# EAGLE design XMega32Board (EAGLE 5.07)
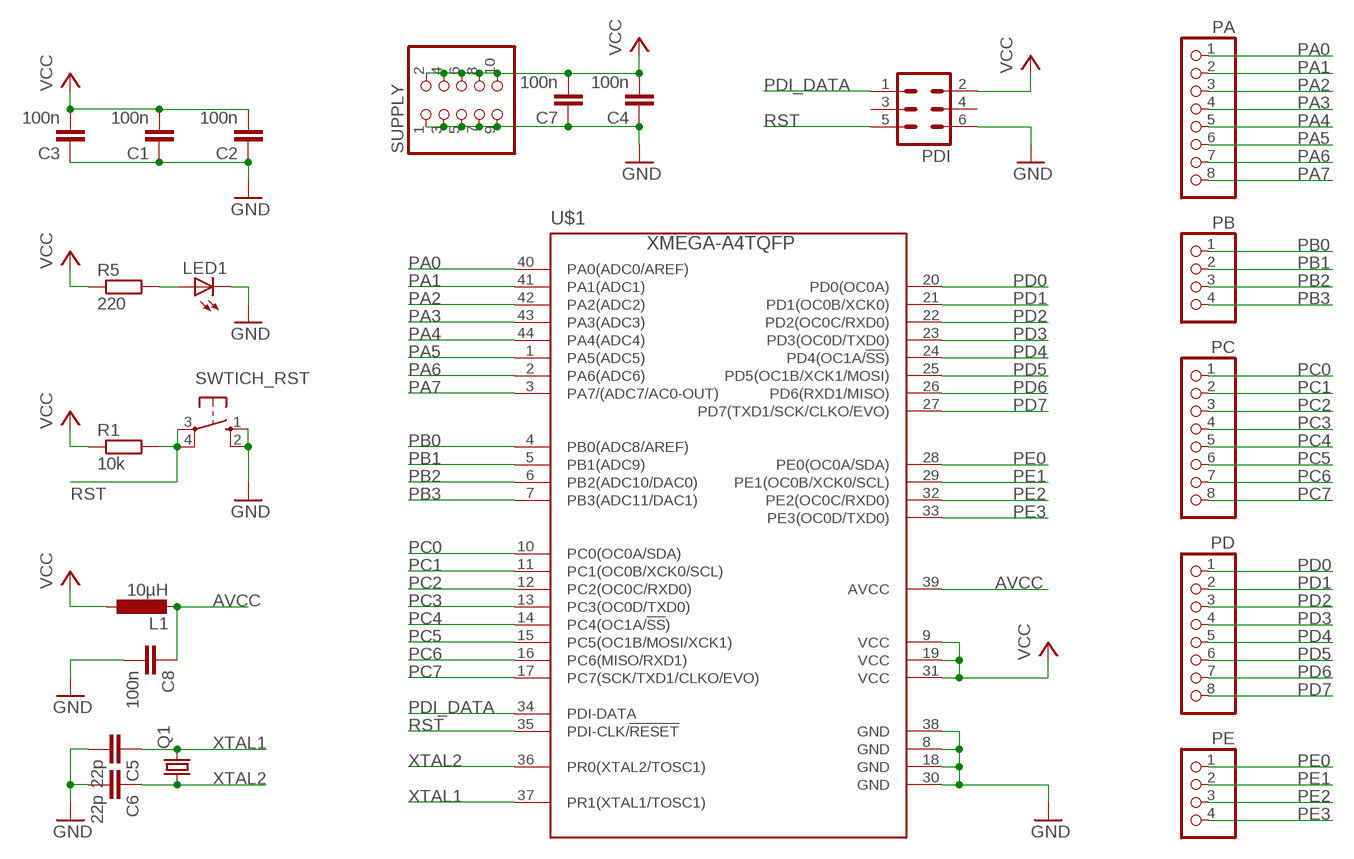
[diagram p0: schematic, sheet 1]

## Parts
C1  100n  C-EUC0805  [C0805]
C2  100n  C-EUC0805  [C0805]
C3  100n  C-EUC0805  [C0805]
C4  100n  C-EUC0805  [C0805]
C5  22p  C-EUC0805  [C0805]
C6  22p  C-EUC0805  [C0805]
C7  100n  C-EUC0805  [C0805]
C8  100n  C-EUC0805  [C0805]
L1  10µH  L-EUL2012C  [L2012C]
LED1  LED3MM  [LED3MM]
PA  PINHD-1X8  [1X08]
PB  PINHD-1X4  [1X04]
PC  PINHD-1X8  [1X08]
PD  PINHD-1X8  [1X08]
PDI  ML6  [ML6]
PE  PINHD-1X4  [1X04]
Q1  CRYSTALHC49S  [HC49/S]
R1  10k  R-EU_R0805  [R0805]
R5  220  R-EU_R0805  [R0805]
SUPPLY  PINHD-2X5  [2X05]
SWTICH_RST  10-XX  [B3F-10XX]
U$1  XMEGA-A4TQFP  [TQFP44]

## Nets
AVCC: C8.1 L1.2 U$1.39(AVCC)
GND: C1.1 C2.1 C3.1 C4.1 C5.2 C6.2 C7.1 C8.2 LED1.K(C) PDI.6 SUPPLY.1 SUPPLY.3 SUPPLY.5 SUPPLY.7 SUPPLY.9 SWTICH_RST.1(S) SWTICH_RST.2(S1) U$1.8(GND) U$1.18(GND) U$1.30(GND) U$1.38(GND)
N$6: LED1.A R5.2
PA0: PA.1 U$1.40(PA0(ADC0/AREF))
PA1: PA.2 U$1.41(PA1(ADC1))
PA2: PA.3 U$1.42(PA2(ADC2))
PA3: PA.4 U$1.43(PA3(ADC3))
PA4: PA.5 U$1.44(PA4(ADC4))
PA5: PA.6 U$1.1(PA5(ADC5))
PA6: PA.7 U$1.2(PA6(ADC6))
PA7: PA.8 U$1.3(PA7/(ADC7/AC0-OUT))
PB0: PB.1 U$1.4(PB0(ADC8/AREF))
PB1: PB.2 U$1.5(PB1(ADC9))
PB2: PB.3 U$1.6(PB2(ADC10/DAC0))
PB3: PB.4 U$1.7(PB3(ADC11/DAC1))
PC0: PC.1 U$1.10(PC0(OC0A/SDA))
PC1: PC.2 U$1.11(PC1(OC0B/XCK0/SCL))
PC2: PC.3 U$1.12(PC2(OC0C/RXD0))
PC3: PC.4 U$1.13(PC3(OC0D/TXD0))
PC4: PC.5 U$1.14(PC4(OC1A/!SS!))
PC5: PC.6 U$1.15(PC5(OC1B/MOSI/XCK1))
PC6: PC.7 U$1.16(PC6(MISO/RXD1))
PC7: PC.8 U$1.17(PC7(SCK/TXD1/CLKO/EVO))
PD0: PD.1 U$1.20(PD0(OC0A))
PD1: PD.2 U$1.21(PD1(OC0B/XCK0))
PD2: PD.3 U$1.22(PD2(OC0C/RXD0))
PD3: PD.4 U$1.23(PD3(OC0D/TXD0))
PD4: PD.5 U$1.24(PD4(OC1A/!SS!))
PD5: PD.6 U$1.25(PD5(OC1B/XCK1/MOSI))
PD6: PD.7 U$1.26(PD6(RXD1/MISO))
PD7: PD.8 U$1.27(PD7(TXD1/SCK/CLKO/EVO))
PDI_DATA: PDI.1 U$1.34(PDI-DATA)
PE0: PE.1 U$1.28(PE0(OC0A/SDA))
PE1: PE.2 U$1.29(PE1(OC0B/XCK0/SCL))
PE2: PE.3 U$1.32(PE2(OC0C/RXD0))
PE3: PE.4 U$1.33(PE3(OC0D/TXD0))
RST: PDI.5 R1.2 SWTICH_RST.3(P) SWTICH_RST.4(P1) U$1.35(PDI-CLK/!RESET)
VCC: C1.2 C2.2 C3.2 C4.2 C7.2 L1.1 PDI.2 R1.1 R5.1 SUPPLY.2 SUPPLY.4 SUPPLY.6 SUPPLY.8 SUPPLY.10 U$1.9(VCC) U$1.19(VCC) U$1.31(VCC)
XTAL1: C5.1 Q1.2 U$1.37(PR1(XTAL1/TOSC1))
XTAL2: C6.1 Q1.1 U$1.36(PR0(XTAL2/TOSC1))
Unconnected: PDI.3 PDI.4

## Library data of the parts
C1-C8 = rcl:C-EU: CAPACITOR, European symbol
L1 = rcl:L-EU: INDUCTOR, European symbol
LED1 = led:LED: LED
PA PC PD = pinhead:PINHD-1X8: PIN HEADER
PB PE = pinhead:PINHD-1X4: PIN HEADER
PDI = con-harting-ml:ML6: HARTING
Q1 = crystal:CRYSTAL: CRYSTAL
R1 R5 = rcl:R-EU_: RESISTOR, European symbol
SUPPLY = pinhead:PINHD-2X5: PIN HEADER
SWTICH_RST = switch-omron:10-XX: OMRON SWITCH
U$1 = avr-7:XMEGA-A4: Atmel XMega A4 series processor

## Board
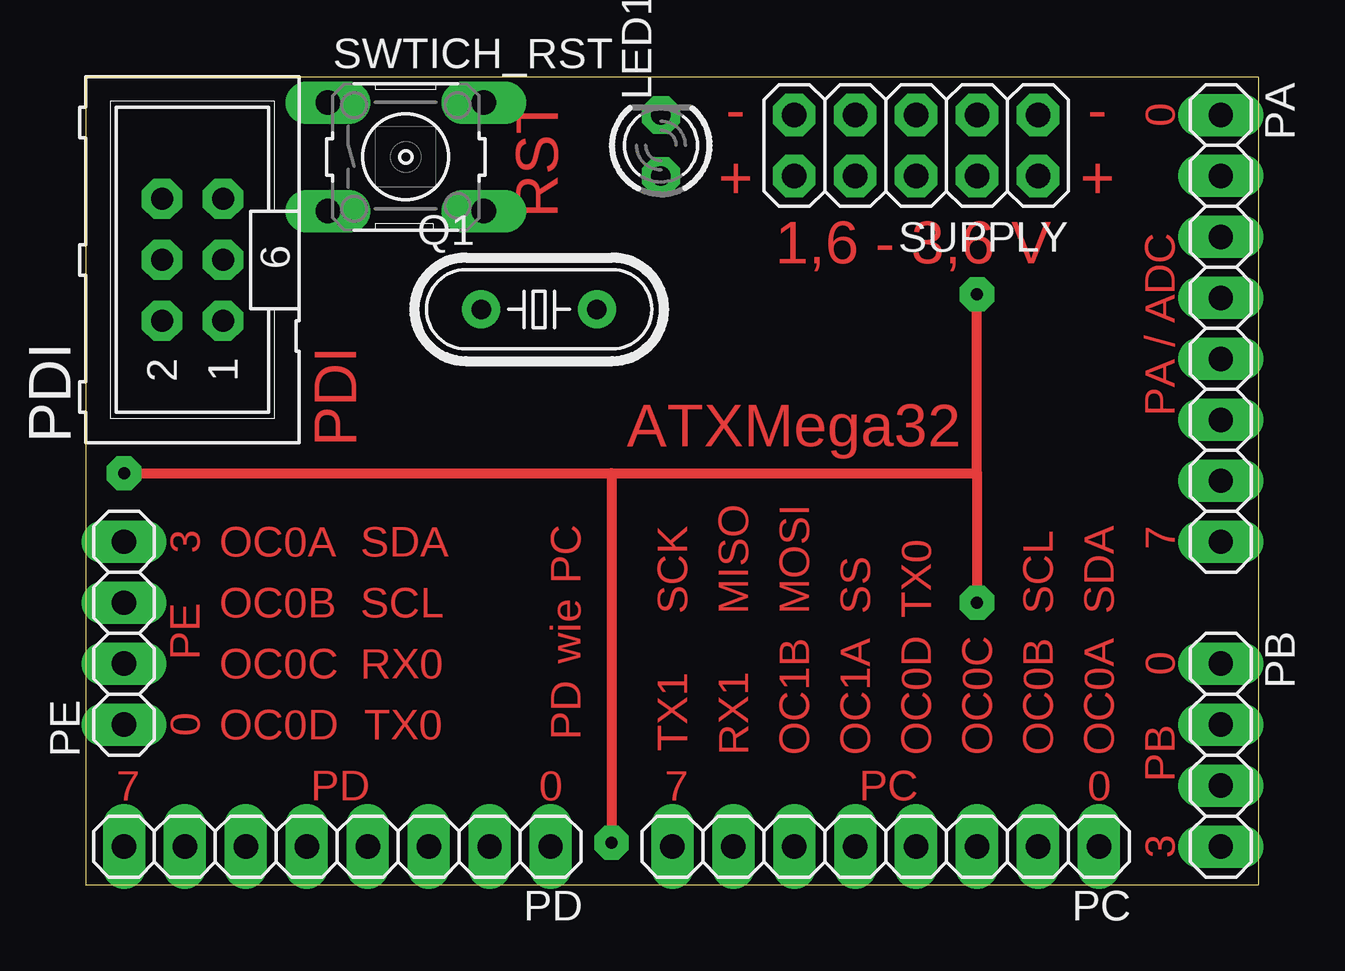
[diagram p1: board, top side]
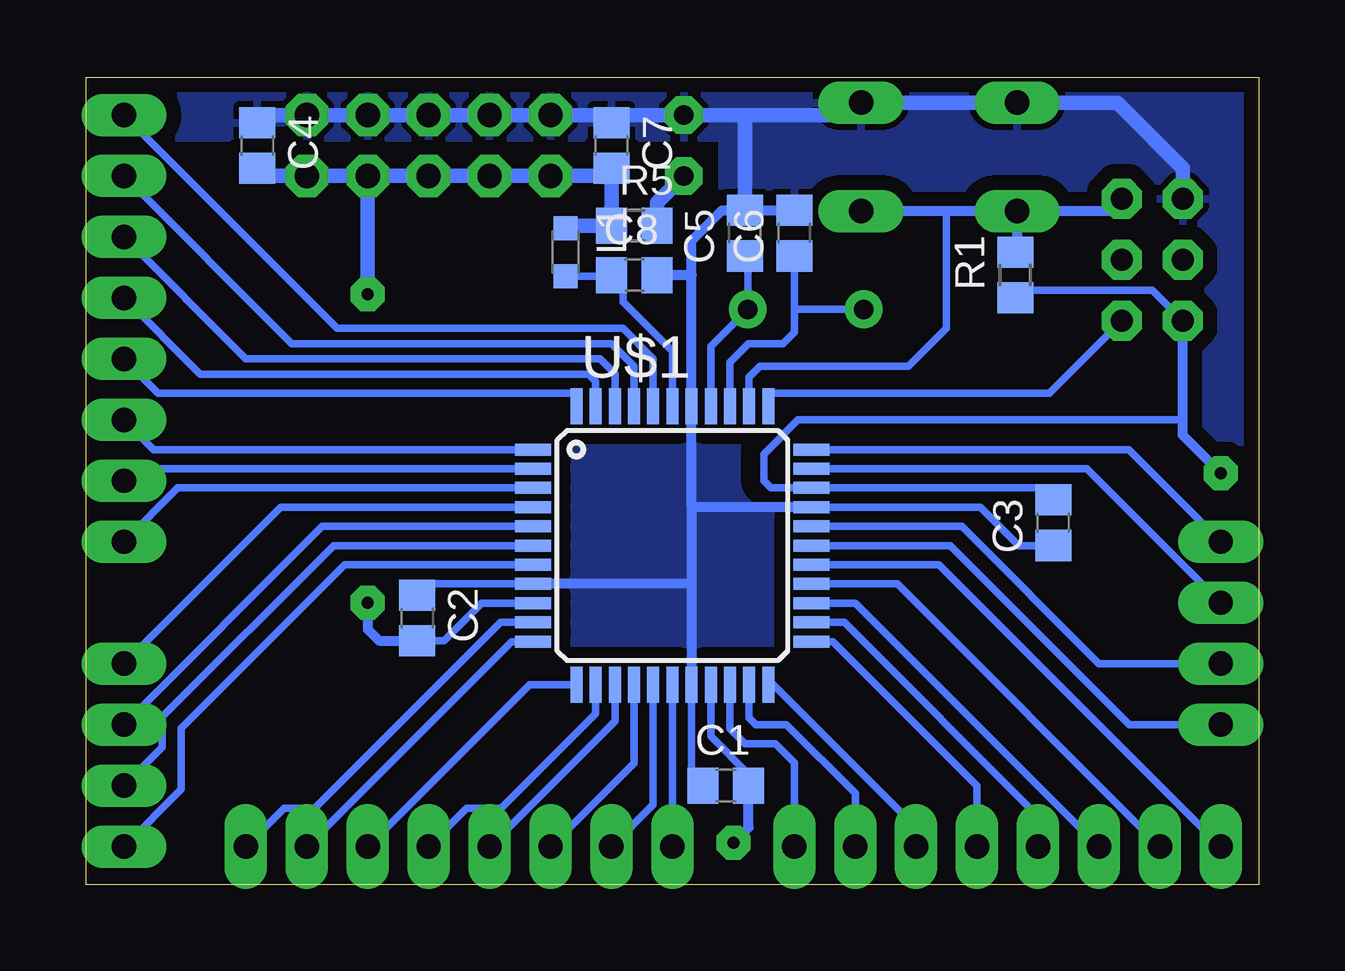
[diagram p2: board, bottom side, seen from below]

Size 48.88 x 33.65 mm. Coordinates in mm from the lower left corner, seen from the top.
Outline: 0,0 48.88,0 48.88,33.65 0,33.65 0,0
Copper layers (1*16): Top 0.035mm / dielectric 1.5mm / Bottom 0.035mm
Design rules "default *": minimum track width 10mil, minimum drill 24mil, track to track 8mil, track to pad 8mil, pad to pad 8mil, via to via 8mil, smd to smd 8mil, copper to edge 10mil, drill to drill 8mil, minimum pad ring 15mil, minimum via ring 8mil, stop-mask expansion 4mil, vias tented up to drill 0mil, thermal gap 10mil

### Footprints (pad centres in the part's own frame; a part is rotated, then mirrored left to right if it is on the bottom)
C0805 = smd 1.3 x 1.5: 1 -0.95,0; 2 0.95,0
L2012C = smd 1 x 1: 1 -1,0; 2 1,0
LED3MM = drill 0.813 octagon: A -1.27,0; K 1.27,0
1X08 = drill 1.016 long: 1 -8.89,0; 2 -6.35,0; 3 -3.81,0; 4 -1.27,0; 5 1.27,0; 6 3.81,0; 7 6.35,0; 8 8.89,0
1X04 = drill 1.016 long: 1 -3.81,0; 2 -1.27,0; 3 1.27,0; 4 3.81,0
ML6 = drill 0.914 octagon: 1 -2.54,-1.27; 2 -2.54,1.27; 3 0,-1.27; 4 0,1.27; 5 2.54,-1.27; 6 2.54,1.27
HC49/S = drill 0.813 round: 1 -2.413,0; 2 2.413,0
R0805 = smd 1.3 x 1.5: 1 -0.95,0; 2 0.95,0
2X05 = drill 1.016 octagon: 1 -5.08,-1.27; 2 -5.08,1.27; 3 -2.54,-1.27; 4 -2.54,1.27; 5 0,-1.27; 6 0,1.27; 7 2.54,-1.27; 8 2.54,1.27; 9 5.08,-1.27; 10 5.08,1.27
B3F-10XX = drill 1.016 long: 1 -3.251,2.261; 2 3.251,2.261; 3 -3.251,-2.261; 4 3.251,-2.261
TQFP44 = smd 1.5 x 0.5: 1 -5.8,4; 2 -5.8,3.2; 3 -5.8,2.4; 4 -5.8,1.6; 5 -5.8,0.8; 6 -5.8,0; 7 -5.8,-0.8; 8 -5.8,-1.6; 9 -5.8,-2.4; 10 -5.8,-3.2; 11 -5.8,-4; 23 5.8,-4; 24 5.8,-3.2; 25 5.8,-2.4; 26 5.8,-1.6; 27 5.8,-0.8; 28 5.8,0; 29 5.8,0.8; 30 5.8,1.6; 31 5.8,2.4; 32 5.8,3.2; 33 5.8,4 | smd 0.5 x 1.5: 12 -4,-5.8; 13 -3.2,-5.8; 14 -2.4,-5.8; 15 -1.6,-5.8; 16 -0.8,-5.8; 17 0,-5.8; 18 0.8,-5.8; 19 1.6,-5.8; 20 2.4,-5.8; 21 3.2,-5.8; 22 4,-5.8; 34 4,5.8; 35 3.2,5.8; 36 2.4,5.8; 37 1.6,5.8; 38 0.8,5.8; 39 0,5.8; 40 -0.8,5.8; 41 -1.6,5.8; 42 -2.4,5.8; 43 -3.2,5.8; 44 -4,5.8

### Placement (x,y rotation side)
C1  22.23,4.13 0 bottom
C2  35.08,11.11 270 bottom
C3  8.57,15.08 90 bottom
C4  41.75,30.8 270 bottom
C5  21.43,27.15 90 bottom
C6  19.37,27.15 90 bottom
C7  26.99,30.8 270 bottom
C8  26.04,25.4 0 bottom
L1  28.89,26.35 270 bottom
LED1  23.97,30.8 90 top
PA  47.31,23.18 270 top
PB  47.31,5.4 270 top
PC  33.34,1.59 180 top
PD  10.48,1.59 180 top
PDI  4.45,26.04 90 top
PE  1.59,10.48 90 top
Q1  18.89,23.97 0 top
R1  10.16,25.4 90 bottom
R5  26.04,27.46 0 bottom
SUPPLY  34.61,30.8 180 top
SWTICH_RST  13.34,30.32 0 top
U$1  24.45,14.13 0 bottom

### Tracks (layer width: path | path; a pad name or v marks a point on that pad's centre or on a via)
AVCC
  Bottom 0.305: U$1.39 24.45,22.23 26.51,24.29 26.51,24.93 C8.1 27.03,25.35 L1.2
GND
  Bottom 0.305: U$1.18 23.65,4.76 C1.1 | U$1.30 11.6,15.73 10,14.13 C3.1 | U$1.8 34.62,12.53 C2.1
  Bottom 0.406: 23.65,25.4 23.65,26.84 22.38,28.1 22.06,28.1 C5.2 | 23.65,25.4 U$1.38 23.65,15.73 | 23.65,25.4 C8.2 | C7.1 26.99,31.91 27.15,32.07 | 23.65,12.53 U$1.18 | U$1.30 23.65,15.73 | 23.65,12.53 U$1.8 | 23.65,15.73 23.65,12.53 | C5.2 C6.2 | C5.2
  Bottom 0.61: LED1.K 27.15,32.07 SUPPLY.9 SUPPLY.7 SUPPLY.5 SUPPLY.3 SUPPLY.1 41.43,32.07 C4.1 | LED1.K | 21.43,32.07 LED1.K | C5.2 21.43,32.07 | 21.43,32.07 17.1,32.07 SWTICH_RST.2 SWTICH_RST.1 5.91,32.58 3.17,29.84 PDI.6
  pour Bottom (isolate 0.61): -0.32,34.13 49.37,34.13 49.37,31.11 22.38,31.11 22.38,27.62 3.17,27.62 3.17,18.26 -0.32,18.26
  pour Bottom (isolate 0.813): 28.89,18.73 19.84,18.73 19.84,9.53 28.89,9.53
N$6
  Bottom 0.61: R5.2 25.09,28.41 LED1.A
PA0
  Bottom 0.305: U$1.40 25.25,21.91 26.51,23.18 38.42,23.18 PA.1
PA1
  Bottom 0.305: U$1.41 26.05,21.6 26.99,22.54 40.32,22.54 PA.2
PA2
  Bottom 0.305: U$1.42 26.85,21.29 27.46,21.91 42.23,21.91 PA.3
PA3
  Bottom 0.305: U$1.43 27.65,20.98 27.94,21.27 44.13,21.27 PA.4
PA4
  Bottom 0.305: U$1.44 28.45,20.45 28.42,20.48 45.88,20.48 PA.5
PA5
  Bottom 0.305: U$1.1 46.07,18.13 PA.6
PA6
  Bottom 0.305: U$1.2 46.81,17.33 PA.7
PA7
  Bottom 0.305: U$1.3 45.07,16.53 PA.8
PB0
  Bottom 0.305: U$1.4 40.79,15.73 PB.1
PB1
  Bottom 0.305: U$1.5 39.05,14.93 PB.2
PB2
  Bottom 0.305: U$1.6 38.58,14.13 45.72,6.99 45.72,5.71 PB.3
PB3
  Bottom 0.305: U$1.7 38.11,13.33 44.93,6.51 44.93,3.97 PB.4
PC0
  Bottom 0.305: U$1.10 31.62,10.93 39.37,3.17 40.64,3.17 PC.1
PC1
  Bottom 0.305: U$1.11 31.15,10.13 PC.2
PC2
  Bottom 0.305: U$1.12 30.41,8.33 PC.3
PC3
  Bottom 0.305: U$1.13 27.65,7.12 31.59,3.17 33.02,3.17 PC.4
PC4
  Bottom 0.305: U$1.14 26.85,6.81 PC.5
PC5
  Bottom 0.305: U$1.15 26.05,5.07 PC.6
PC6
  Bottom 0.305: U$1.16 25.25,3.33 PC.7
PC7
  Bottom 0.305: PC.8 U$1.17
PD0
  Bottom 0.305: U$1.20 22.05,6.49 21.43,5.87 20.16,5.87 19.37,5.08 PD.1
PD1
  Bottom 0.305: PD.2 16.83,3.81 19.68,6.67 20.95,6.67 21.25,6.96 U$1.21
PD2
  Bottom 0.305: U$1.22 20.23,8.33 14.29,2.38 PD.3
PD3
  Bottom 0.305: U$1.23 17.75,10.13 11.75,4.13 PD.4
PD4
  Bottom 0.305: U$1.24 17.28,10.93 9.21,2.86 PD.5
PD5
  Bottom 0.305: U$1.25 16.81,11.73 PD.6
PD6
  Bottom 0.305: U$1.26 15.07,12.53 PD.7
PD7
  Bottom 0.305: U$1.27 13.33,13.33 PD.8
PDI_DATA
  Bottom 0.305: U$1.34 20.45,20.35 20.32,20.48 8.73,20.48 PDI.1
PE0
  Bottom 0.305: U$1.28 12.86,14.13 5.4,6.67 PE.1
PE1
  Bottom 0.305: U$1.29 12.39,14.93 6.67,9.21 PE.2
PE2
  Bottom 0.305: U$1.32 7.17,17.33 PE.3
PE3
  Bottom 0.305: U$1.33 5.43,18.13 PE.4
RST
  Bottom 0.305: U$1.35 21.25,21.14 20.8,21.59 14.61,21.59 13.02,23.18 13.02,28.06 12.54,28.06
  Bottom 0.406: SWTICH_RST.3 6.23,28.06 PDI.5 | SWTICH_RST.3 12.54,28.06 SWTICH_RST.4 | SWTICH_RST.3 10.08,26.43 R1.2
VCC  (via drill 0.5 pad 1.42)
  Top 0.406: 21.91,17.14 v21.91,1.75 | v1.59,17.14 21.91,17.14 | 37.15,17.14 v37.15,24.61 | 21.91,17.14 37.15,17.14 | 37.15,17.14 v37.15,11.75
  Bottom 0.305: PDI.2 4.45,24.77 9.69,24.77 R1.1 | U$1.19 22.85,6.18 21.27,4.6 21.27,4.28 C1.2 | 3.17,19.21 3.17,19.37 19.21,19.37 20.64,17.94 20.64,16.83 20.34,16.53 U$1.31 9.07,16.53 C3.2 | U$1.9 32.4,11.73 33.97,10.16 C2.2
  Bottom 0.406: C1.2 21.27,2.38 v21.91,1.75 | PDI.2 3.17,19.21 3.17,18.73 v1.59,17.14 | C2.2 36.67,10.16 37.15,10.64 v37.15,11.75
  Bottom 0.61: SUPPLY.4 SUPPLY.2 41.43,29.53 C4.2 | L1.1 28.78,27.46 R5.1 C7.2 27.31,29.53 SUPPLY.10 SUPPLY.8 SUPPLY.6 SUPPLY.4 | v37.15,24.61 SUPPLY.4
XTAL1
  Bottom 0.305: U$1.37 22.85,22.43 Q1.2 21.3,26.07 C5.1
XTAL2
  Bottom 0.305: 19.37,23.97 C6.1 | Q1.1 19.37,23.97 | 19.37,23.97 | U$1.36 22.05,21.77 21.27,22.54 19.84,22.54 19.37,23.02 19.37,23.97 | 19.37,23.97

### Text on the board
Top: 0 | - | - | + | + | RST | 1,6 - 3,6 V | PA / ADC | PDI | ATXMega32 | 3 | OC0A | SDA | 7 | PC | OC0B | SCL | SCK | MISO | MOSI | SS | TX0 | SCL | SDA | PE | OC0C | RX0 | wie | 0 | 0 | OC0D | TX0 | PD | TX1 | RX1 | OC1B | OC1A | OC0D | OC0C | OC0B | OC0A | PB | 7 | PD | 0 | 7 | PC | 0 | 3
